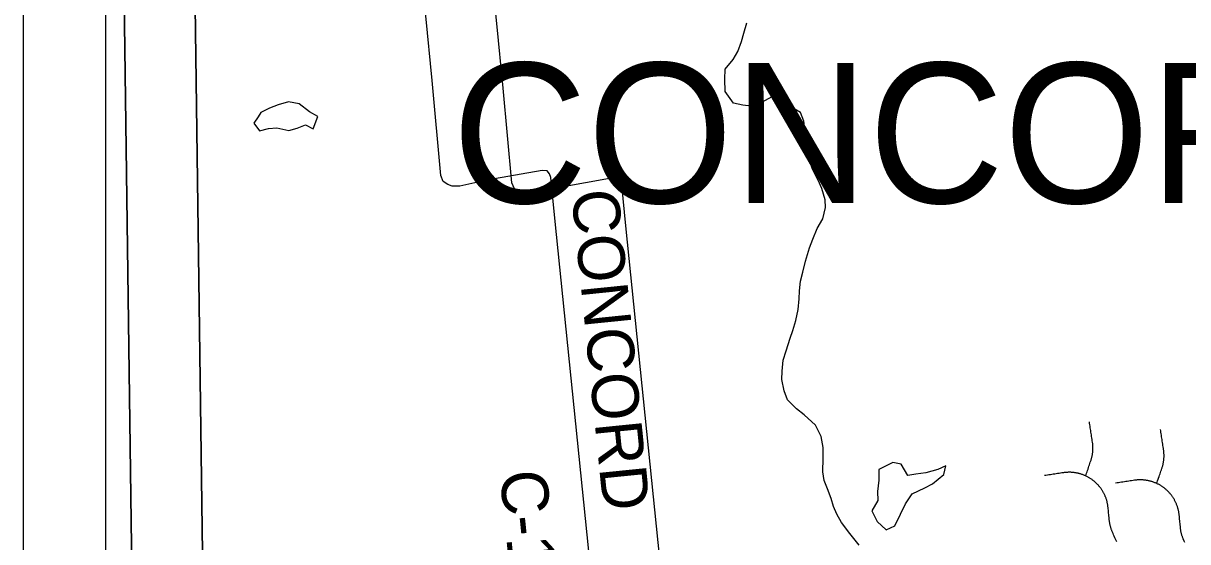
# Model space of a CAD drawing. Extents: x -38.2 to 41.9, y -4 to 24.9.
# Drawn here: x 2 to 3.416, y 19.582 to 20.213 of the extents above; entities that cross this region are included whole.
import ezdxf

# ---------------------------------------------------------------- set-up
doc = ezdxf.new("R2010")
doc.units = 0
for name, color, linetype in [('GM_X_County_Road', 7, 'Continuous'), ('GM_X_County_Road_Text', 7, 'Continuous'), ('GM_X_Interchange_Ramps', 7, 'Continuous'), ('GM_X_Minor_Lake', 7, 'Continuous'), ('GM_X_Minor_River', 7, 'Continuous'), ('GM_X_State_Location', 7, 'Continuous'), ('GM_X_Township_Road', 7, 'Continuous'), ('GM_X_Township_Road_Text', 7, 'Continuous'), ('GM_X_Township_Text', 7, 'Continuous'), ('SH_Cut_Line', 7, 'Continuous'), ('SH_Data', 7, 'Continuous')]:
    doc.layers.add(name, color=color, linetype=linetype)

msp = doc.modelspace()

# ---------------------------------------------------------------- linework, layer by layer
at = {"layer": 'GM_X_County_Road'}
msp.add_lwpolyline([(2.7015, 19.4355), (2.6464, 19.9755), (2.6416, 20.0251), (2.6399, 20.0297), (2.6373, 20.0331), (2.6311, 20.0337), (2.5636, 20.0217), (2.531, 20.0146), (2.5216, 20.0146), (2.5162, 20.0164), (2.5108, 20.0203), (2.5077, 20.0277), (2.4972, 20.143), (2.4895, 20.2217), (2.4876, 20.2415)], dxfattribs=at)
at = {"layer": 'GM_X_Interchange_Ramps'}
for points in [[(5.0183, 19.2401), (5.0869, 20.3321), (5.1243, 20.9), (2.1103, 20.9), (2.1124, 20.4526), (2.1223, 20.2725), (2.1339, 19.396)], [(5.1048, 19.2309), (5.1734, 20.3229), (5.2114, 20.9), (2.1968, 20.9), (2.1989, 20.4434), (2.2088, 20.2633), (2.2204, 19.3868)]]:
    msp.add_lwpolyline(points, dxfattribs=at)
for points in [[(2.1, 20.4515), (2.1, 14.1636), (2.1303, 14.1626), (2.1303, 14.1722), (2.1335, 15.4167), (2.1334, 15.4951), (2.1328, 15.831), (2.1521, 16.6664), (2.1489, 17.073), (2.1485, 17.1357), (2.1484, 17.1455), (2.1486, 17.1556), (2.1569, 17.5704), (2.1549, 17.5972), (2.1521, 17.6416), (2.1422, 17.7563), (2.1427, 17.838), (2.1429, 18.1709), (2.1421, 18.2952), (2.138, 18.8976), (2.1339, 19.396), (2.1223, 20.2725), (2.1124, 20.4526)], [(2.1, 20.4344), (2.1, 14.1575), (2.2168, 14.1534), (2.2168, 14.163), (2.22, 15.4075), (2.2199, 15.4859), (2.2193, 15.8218), (2.2386, 16.6572), (2.2354, 17.0638), (2.235, 17.1266), (2.2349, 17.1363), (2.2351, 17.1464), (2.2434, 17.5612), (2.2414, 17.5881), (2.2386, 17.6324), (2.2287, 17.7471), (2.2291, 17.8288), (2.2294, 18.1617), (2.2286, 18.286), (2.2245, 18.8884), (2.2204, 19.3868), (2.2088, 20.2633), (2.1989, 20.4434)]]:
    msp.add_lwpolyline(points, close=True, dxfattribs=at)
at = {"layer": 'GM_X_Minor_Lake'}
for points in [[(2.3525, 20.0841), (2.3583, 20.0993), (2.3481, 20.105), (2.3356, 20.1145), (2.3227, 20.1172), (2.3101, 20.1135), (2.2995, 20.1093), (2.2888, 20.1041), (2.2855, 20.099)], [(2.2855, 20.099), (2.2804, 20.0912), (2.2872, 20.0817), (2.2983, 20.0847), (2.3085, 20.0854), (2.3229, 20.0823), (2.3332, 20.085), (2.3431, 20.0891), (2.3525, 20.0841)], [(3.0772, 19.6344), (3.0813, 19.6403), (3.0965, 19.6478), (3.106, 19.6527), (3.1197, 19.6637), (3.122, 19.6743), (3.1125, 19.6701), (3.0977, 19.666), (3.0855, 19.6641), (3.0757, 19.6627), (3.0677, 19.6763), (3.0575, 19.6786), (3.0404, 19.67)], [(3.0404, 19.67), (3.0407, 19.6571), (3.0391, 19.6431), (3.0395, 19.6321), (3.0322, 19.6196), (3.0387, 19.6067), (3.0496, 19.5964), (3.0599, 19.6013), (3.0668, 19.6157), (3.0729, 19.6282), (3.0772, 19.6344)]]:
    msp.add_lwpolyline(points, dxfattribs=at)
at = {"layer": 'GM_X_Minor_River'}
for points in [[(2.8535, 20.157), (2.8634, 20.1687), (2.8691, 20.1785), (2.8737, 20.1903), (2.8764, 20.2005), (2.8802, 20.2134)], [(3.0166, 19.5779), (3.0052, 19.5923), (2.995, 19.6053), (2.9897, 19.6155), (2.9856, 19.625), (2.9826, 19.6345), (2.978, 19.6463), (2.9739, 19.6565), (2.9724, 19.6671), (2.9728, 19.6838), (2.9729, 19.6967), (2.9706, 19.71), (2.9635, 19.724), (2.9498, 19.7366), (2.9404, 19.7438), (2.9294, 19.7545), (2.9256, 19.7658), (2.9226, 19.7795), (2.923, 19.7894), (2.9242, 19.803), (2.928, 19.8144), (2.9326, 19.8295), (2.9361, 19.839), (2.9395, 19.8511), (2.9426, 19.8647), (2.9438, 19.8776), (2.9442, 19.8871), (2.9454, 19.8992), (2.9481, 19.9098), (2.9515, 19.9235), (2.9561, 19.9394), (2.9603, 19.95), (2.9657, 19.9629), (2.9726, 19.975), (2.9756, 19.9886), (2.9753, 19.9981), (2.9711, 20.0118), (2.9666, 20.022), (2.9598, 20.0353), (2.9561, 20.0456), (2.9531, 20.0554), (2.9523, 20.0702), (2.9509, 20.0812), (2.9494, 20.0937), (2.9452, 20.104), (2.9335, 20.1112), (2.9229, 20.123), (2.9111, 20.1238), (2.897, 20.1159), (2.8853, 20.1117), (2.875, 20.1129), (2.864, 20.1156), (2.8538, 20.1297), (2.8531, 20.1445), (2.8535, 20.157)]]:
    msp.add_lwpolyline(points, dxfattribs=at)
at = {"layer": 'GM_X_State_Location'}
for points in [[(3.3786, 19.653), (3.3791, 19.6546), (3.3797, 19.6563), (3.3803, 19.658), (3.3809, 19.6596), (3.3814, 19.6613), (3.382, 19.663), (3.3826, 19.6647), (3.3832, 19.6663), (3.3837, 19.668), (3.3843, 19.6697), (3.3849, 19.6713), (3.3852, 19.6721), (3.3854, 19.6729), (3.3856, 19.6737), (3.3859, 19.6744), (3.3861, 19.6752), (3.3863, 19.676), (3.3864, 19.6768), (3.3866, 19.6776), (3.3867, 19.6784), (3.3869, 19.6792), (3.387, 19.68), (3.3871, 19.6808), (3.3872, 19.6816), (3.3873, 19.6825), (3.3874, 19.6833), (3.3874, 19.6841), (3.3875, 19.6849), (3.3875, 19.6857), (3.3875, 19.6865), (3.3875, 19.6873), (3.3875, 19.6881), (3.3874, 19.689), (3.3874, 19.6898), (3.3873, 19.6906), (3.3873, 19.6914), (3.3872, 19.6922), (3.3871, 19.693), (3.387, 19.6938), (3.3867, 19.6956), (3.3864, 19.6974), (3.3862, 19.6992), (3.3859, 19.7009), (3.3856, 19.7027), (3.3854, 19.7045), (3.3851, 19.7063), (3.3848, 19.708), (3.3845, 19.7098), (3.3843, 19.7116), (3.384, 19.7134), (3.3837, 19.7152), (3.3835, 19.7169), (3.3832, 19.7187)], [(3.4127, 19.5812), (3.4119, 19.5829), (3.4112, 19.5846), (3.4109, 19.5854), (3.4106, 19.5861), (3.4103, 19.5868), (3.41, 19.5875), (3.4098, 19.5883), (3.4095, 19.589), (3.4093, 19.5898), (3.409, 19.5905), (3.4088, 19.5913), (3.4086, 19.5921), (3.4085, 19.5928), (3.4083, 19.5936), (3.4081, 19.5944), (3.408, 19.5951), (3.4078, 19.5959), (3.4077, 19.5967), (3.4076, 19.5975), (3.4075, 19.5982), (3.4074, 19.599), (3.4073, 19.6007), (3.4071, 19.6025), (3.4069, 19.6042), (3.4068, 19.6059), (3.4066, 19.6077), (3.4064, 19.6094), (3.4062, 19.6111), (3.4061, 19.6129), (3.4059, 19.6146), (3.4058, 19.6154), (3.4057, 19.6162), (3.4056, 19.617), (3.4055, 19.6178), (3.4053, 19.6187), (3.4052, 19.6195), (3.405, 19.6203), (3.4048, 19.6211), (3.4046, 19.6219), (3.4044, 19.6227), (3.4042, 19.6234), (3.4039, 19.6242), (3.4037, 19.625), (3.4034, 19.6258), (3.4031, 19.6266), (3.4028, 19.6273), (3.4025, 19.6281), (3.4022, 19.6288), (3.4019, 19.6296), (3.4015, 19.6303), (3.4012, 19.6311), (3.4008, 19.6318), (3.4004, 19.6325), (3.4, 19.6333), (3.3996, 19.634), (3.3992, 19.6347), (3.3987, 19.6354), (3.3983, 19.6361), (3.3978, 19.6367), (3.3973, 19.6374), (3.3969, 19.6381), (3.3964, 19.6387), (3.3959, 19.6394), (3.3953, 19.64), (3.3948, 19.6407), (3.3943, 19.6413), (3.3937, 19.6419), (3.3932, 19.6425), (3.3926, 19.6431), (3.392, 19.6437), (3.3914, 19.6442), (3.3908, 19.6448), (3.3902, 19.6454), (3.3896, 19.6459), (3.389, 19.6464), (3.3883, 19.6469), (3.3877, 19.6475), (3.387, 19.6479), (3.3864, 19.6484), (3.3857, 19.6489), (3.385, 19.6494), (3.3843, 19.6498), (3.3836, 19.6503), (3.3829, 19.6507), (3.3822, 19.6511), (3.3815, 19.6515), (3.3808, 19.6519), (3.38, 19.6523), (3.3793, 19.6526), (3.3786, 19.653), (3.3778, 19.6533), (3.3771, 19.6536), (3.3763, 19.6539), (3.3756, 19.6542), (3.3748, 19.6545), (3.374, 19.6548), (3.3733, 19.655), (3.3725, 19.6553), (3.3717, 19.6555), (3.3709, 19.6557), (3.3701, 19.6559), (3.3693, 19.6561), (3.3685, 19.6563), (3.3677, 19.6564), (3.367, 19.6566), (3.3661, 19.6567), (3.3653, 19.6569), (3.3645, 19.657), (3.3637, 19.6571), (3.3629, 19.6571), (3.3621, 19.6572), (3.3613, 19.6572), (3.3605, 19.6573), (3.3597, 19.6573), (3.3589, 19.6573), (3.3581, 19.6573), (3.3572, 19.6573), (3.3564, 19.6573), (3.3556, 19.6572), (3.3548, 19.6572), (3.354, 19.6571), (3.3532, 19.657), (3.3524, 19.6569), (3.3516, 19.6568), (3.3498, 19.6565), (3.348, 19.6562), (3.3463, 19.656), (3.3445, 19.6557), (3.3427, 19.6554), (3.341, 19.6552), (3.3392, 19.6549), (3.3374, 19.6546), (3.3357, 19.6544), (3.3339, 19.6541), (3.3321, 19.6538), (3.3304, 19.6536), (3.3286, 19.6533)]]:
    msp.add_lwpolyline(points, dxfattribs=at)
at = {"layer": 'GM_X_Township_Road'}
for points in [[(3.2921, 19.6622), (3.2927, 19.6638), (3.2932, 19.6655), (3.2938, 19.6672), (3.2944, 19.6688), (3.295, 19.6705), (3.2955, 19.6722), (3.2961, 19.6738), (3.2967, 19.6755), (3.2973, 19.6772), (3.2978, 19.6788), (3.2984, 19.6805), (3.2987, 19.6813), (3.2989, 19.6821), (3.2992, 19.6828), (3.2994, 19.6836), (3.2996, 19.6844), (3.2998, 19.6852), (3.3, 19.686), (3.3001, 19.6868), (3.3003, 19.6876), (3.3004, 19.6884), (3.3005, 19.6892), (3.3006, 19.69), (3.3007, 19.6908), (3.3008, 19.6916), (3.3009, 19.6924), (3.3009, 19.6933), (3.301, 19.6941), (3.301, 19.6949), (3.301, 19.6957), (3.301, 19.6965), (3.301, 19.6973), (3.301, 19.6981), (3.3009, 19.699), (3.3009, 19.6998), (3.3008, 19.7006), (3.3007, 19.7014), (3.3006, 19.7022), (3.3005, 19.703), (3.3002, 19.7048), (3.2999, 19.7066), (3.2997, 19.7083), (3.2994, 19.7101), (3.2991, 19.7119), (3.2989, 19.7137), (3.2986, 19.7155), (3.2983, 19.7172), (3.2981, 19.719), (3.2978, 19.7208), (3.2975, 19.7226), (3.2973, 19.7244), (3.297, 19.7261), (3.2967, 19.7279)], [(3.33, 19.5818), (3.3292, 19.5835), (3.3285, 19.5853), (3.3277, 19.587), (3.327, 19.5887), (3.3262, 19.5904), (3.3255, 19.5921), (3.3247, 19.5938), (3.3244, 19.5945), (3.3241, 19.5953), (3.3238, 19.596), (3.3235, 19.5967), (3.3233, 19.5975), (3.323, 19.5982), (3.3228, 19.599), (3.3226, 19.5997), (3.3224, 19.6005), (3.3222, 19.6012), (3.322, 19.602), (3.3218, 19.6028), (3.3216, 19.6035), (3.3215, 19.6043), (3.3214, 19.6051), (3.3212, 19.6059), (3.3211, 19.6066), (3.321, 19.6074), (3.3209, 19.6082), (3.3208, 19.6099), (3.3206, 19.6117), (3.3204, 19.6134), (3.3203, 19.6151), (3.3201, 19.6169), (3.3199, 19.6186), (3.3198, 19.6203), (3.3196, 19.622), (3.3194, 19.6238), (3.3193, 19.6246), (3.3192, 19.6254), (3.3191, 19.6262), (3.319, 19.627), (3.3188, 19.6278), (3.3187, 19.6286), (3.3185, 19.6295), (3.3183, 19.6303), (3.3181, 19.6311), (3.3179, 19.6318), (3.3177, 19.6326), (3.3174, 19.6334), (3.3172, 19.6342), (3.3169, 19.635), (3.3166, 19.6357), (3.3163, 19.6365), (3.316, 19.6373), (3.3157, 19.638), (3.3154, 19.6388), (3.315, 19.6395), (3.3147, 19.6403), (3.3143, 19.641), (3.3139, 19.6417), (3.3135, 19.6424), (3.3131, 19.6432), (3.3127, 19.6439), (3.3122, 19.6446), (3.3118, 19.6453), (3.3113, 19.6459), (3.3109, 19.6466), (3.3104, 19.6473), (3.3099, 19.6479), (3.3094, 19.6486), (3.3089, 19.6492), (3.3083, 19.6498), (3.3078, 19.6505), (3.3072, 19.6511), (3.3067, 19.6517), (3.3061, 19.6523), (3.3055, 19.6529), (3.3049, 19.6534), (3.3043, 19.654), (3.3037, 19.6545), (3.3031, 19.6551), (3.3025, 19.6556), (3.3018, 19.6561), (3.3012, 19.6566), (3.3006, 19.6571), (3.2999, 19.6576), (3.2992, 19.6581), (3.2985, 19.6586), (3.2978, 19.659), (3.2971, 19.6594), (3.2964, 19.6599), (3.2957, 19.6603), (3.295, 19.6607), (3.2943, 19.6611), (3.2936, 19.6614), (3.2928, 19.6618), (3.2921, 19.6622), (3.2913, 19.6625), (3.2906, 19.6628), (3.2898, 19.6631), (3.2891, 19.6634), (3.2883, 19.6637), (3.2876, 19.664), (3.2868, 19.6642), (3.286, 19.6645), (3.2852, 19.6647), (3.2844, 19.6649), (3.2836, 19.6651), (3.2829, 19.6653), (3.2821, 19.6655), (3.2813, 19.6656), (3.2805, 19.6658), (3.2797, 19.6659), (3.2789, 19.666), (3.2781, 19.6661), (3.2773, 19.6662), (3.2764, 19.6663), (3.2756, 19.6664), (3.2748, 19.6664), (3.274, 19.6665), (3.2732, 19.6665), (3.2724, 19.6665), (3.2716, 19.6665), (3.2708, 19.6665), (3.2699, 19.6664), (3.2691, 19.6664), (3.2683, 19.6663), (3.2675, 19.6663), (3.2667, 19.6662), (3.2659, 19.6661), (3.2651, 19.666), (3.2633, 19.6657), (3.2616, 19.6654), (3.2598, 19.6652), (3.258, 19.6649), (3.2563, 19.6646), (3.2545, 19.6644), (3.2527, 19.6641), (3.251, 19.6638), (3.2492, 19.6636), (3.2474, 19.6633), (3.2457, 19.663), (3.2439, 19.6628), (3.2421, 19.6625)]]:
    msp.add_lwpolyline(points, dxfattribs=at)
at = {"layer": 'GM_X_Township_Road_Text'}
msp.add_lwpolyline([(2.7879, 19.4263), (2.7328, 19.9663), (2.728, 20.016), (2.7263, 20.0205), (2.7238, 20.0239), (2.7175, 20.0245), (2.65, 20.0126), (2.6174, 20.0055), (2.6081, 20.0055), (2.6027, 20.0072), (2.5973, 20.0111), (2.5942, 20.0185), (2.5836, 20.1338), (2.5759, 20.2125), (2.574, 20.2323)], dxfattribs=at)
at = {"layer": 'SH_Cut_Line'}
msp.add_lwpolyline([(2.1103, 20.9), (2.1, 20.9), (2.1, 14.1636), (2.1303, 14.1626), (2.1303, 14.1722), (2.1335, 15.4167), (2.1334, 15.4951), (2.1328, 15.831), (2.1521, 16.6664), (2.1489, 17.073), (2.1485, 17.1357), (2.1484, 17.1455), (2.1486, 17.1556), (2.1569, 17.5704), (2.1549, 17.5972), (2.1521, 17.6416), (2.1422, 17.7563), (2.1427, 17.838), (2.1429, 18.1709), (2.1421, 18.2952), (2.138, 18.8976), (2.1339, 19.396), (2.1223, 20.2725), (2.1124, 20.4526)], close=True, dxfattribs=at)
msp.add_lwpolyline([(8.9, 20.9), (2.1103, 20.9), (2.1124, 20.4526), (2.1223, 20.2725), (2.1339, 19.396), (2.138, 18.8976), (2.1421, 18.2952), (2.1429, 18.1709), (2.1427, 17.838), (2.1422, 17.7563), (2.1521, 17.6416), (2.1549, 17.5972), (2.1569, 17.5704), (2.1486, 17.1556)], dxfattribs=at)
at = {"layer": 'SH_Data'}
for p, q in [((2, 21), (2, 14)), ((2.1, 20.9), (2.1, 14.1))]:
    msp.add_line(p, q, dxfattribs=at)

# ---------------------------------------------------------------- texts
at = {"layer": 'GM_X_County_Road_Text'}
for s, rotation, p in [('CONCORD', 275.7674, (2.6665, 20.0081)), ('C-129', 275.7928, (2.5793, 19.6666))]:
    msp.add_text(s, height=0.05682, rotation=rotation, dxfattribs=at).set_placement(p)
at = {"layer": 'GM_X_Township_Text'}
msp.add_text('CONCORD', height=0.17045, rotation=0, dxfattribs=at).set_placement((2.5215, 19.994))

doc.saveas('drawing.dxf')
